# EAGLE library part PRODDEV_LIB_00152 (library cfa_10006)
CFAG12864A-CFH-TN, 128x64 Red/Green/Blue
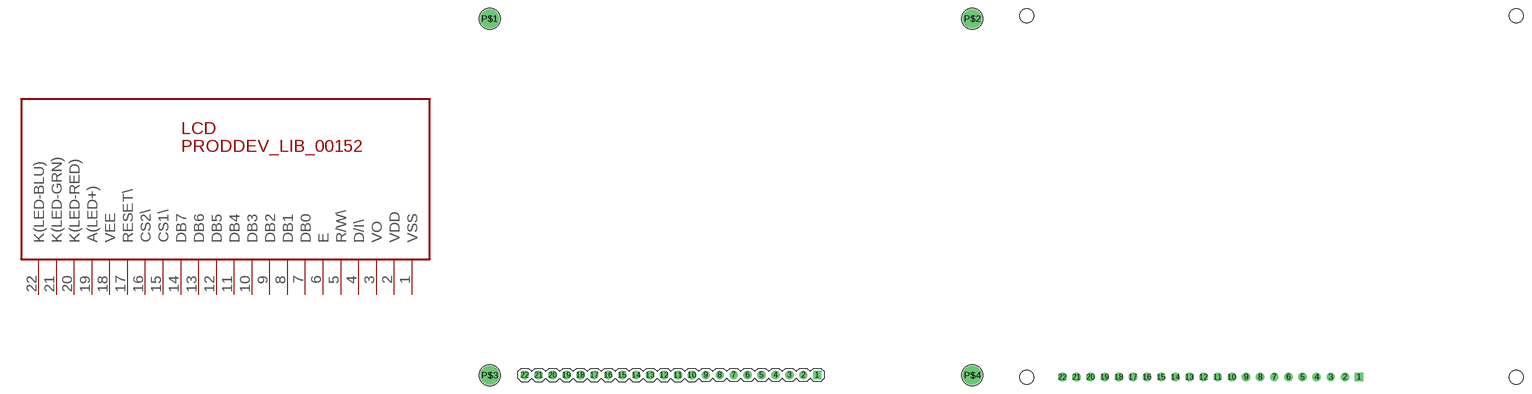
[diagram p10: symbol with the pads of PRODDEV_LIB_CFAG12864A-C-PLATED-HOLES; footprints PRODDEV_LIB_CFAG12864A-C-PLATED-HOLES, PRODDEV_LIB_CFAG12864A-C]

Designator prefix LCD

## PRODDEV_LIB_00152  [PRODDEV_LIB_CFAG12864A-C-PLATED-HOLES]
1  VSS  pwr
2  VDD  pwr
3  VO  pas
4  D/I\  in
5  R/W\  in
6  E  in
7  DB0
8  DB1
9  DB2
10  DB3
11  DB4
12  DB5
13  DB6
14  DB7
15  CS1\  in
16  CS2\  in
17  RESET\  in
18  VEE  pas
19  A(LED+)  pas
20  K(LED-RED)  pas
21  K(LED-GRN)  pas
22  K(LED-BLU)  pas

## PRODDEV_LIB_00152NON-PLATED-HOLES  [PRODDEV_LIB_CFAG12864A-C]
Pads as for PRODDEV_LIB_CFAG12864A-C-PLATED-HOLES

## Footprint PRODDEV_LIB_CFAG12864A-C-PLATED-HOLES (pad centres in mm)
drill 1 square: 1 0,0
drill 1 round: 2 -2.54,0; 3 -5.08,0; 4 -7.62,0; 5 -10.16,0; 6 -12.7,0; 7 -15.24,0; 8 -17.78,0; 9 -20.32,0; 10 -22.86,0; 11 -25.4,0; 12 -27.94,0; 13 -30.48,0; 14 -33.02,0; 15 -35.56,0; 16 -38.1,0; 17 -40.64,0; 18 -43.18,0; 19 -45.72,0; 20 -48.26,0; 21 -50.8,0; 22 -53.34,0
drill 2.5 round: P$1 -59.73,64.96; P$2 28.27,64.96; P$3 -59.73,-0.04; P$4 28.27,-0.04

## Footprint PRODDEV_LIB_CFAG12864A-C (pad centres in mm)
drill 1 square: 1 0,0
drill 1 round: 2 -2.54,0; 3 -5.08,0; 4 -7.62,0; 5 -10.16,0; 6 -12.7,0; 7 -15.24,0; 8 -17.78,0; 9 -20.32,0; 10 -22.86,0; 11 -25.4,0; 12 -27.94,0; 13 -30.48,0; 14 -33.02,0; 15 -35.56,0; 16 -38.1,0; 17 -40.64,0; 18 -43.18,0; 19 -45.72,0; 20 -48.26,0; 21 -50.8,0; 22 -53.34,0
hole 2.5 at -59.73,-0.04
hole 2.5 at 28.27,-0.04
hole 2.5 at 28.27,64.96
hole 2.5 at -59.73,64.96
